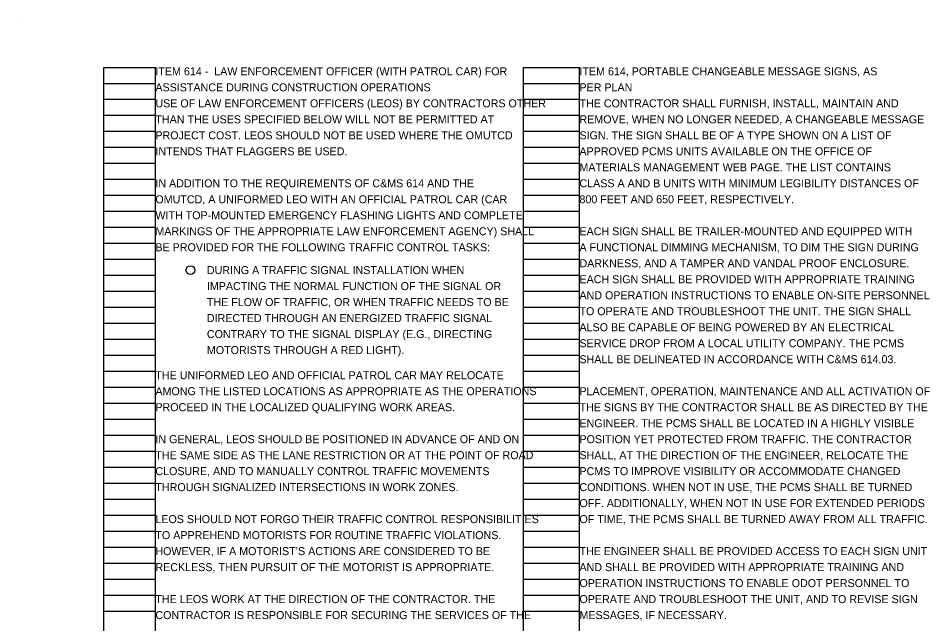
# Model space of a CAD drawing. Extents: x 0 to 32, y -44 to 21.1.
# Drawn here: x 0 to 15.95, y -10.6 to 0 of the extents above; entities that cross this region are included whole.
import ezdxf

# ---------------------------------------------------------------- set-up
doc = ezdxf.new("R2010")
doc.units = 0
doc.layers.add('SH_Data', color=7, linetype='Continuous')
doc.layers.add('SH_Text', color=7, linetype='Continuous')

msp = doc.modelspace()

# ---------------------------------------------------------------- linework, layer by layer
at = {"layer": 'SH_Data'}
for p, q in [((0, 0), (0, 0)), ((1.5, -21.02), (1.5, -0.86)), ((1.5, -0.86), (2.4, -0.86)), ((2.4, -21.02), (2.4, -0.86)), ((8.84, -21.02), (8.84, -0.86)), ((8.84, -0.86), (9.82, -0.86)), ((9.82, -21.02), (9.82, -0.86)), ((1.5, -1.14), (2.4, -1.14)), ((8.84, -1.14), (9.82, -1.14)), ((1.5, -1.42), (2.4, -1.42)), ((8.84, -1.42), (9.82, -1.42)), ((1.5, -1.7), (2.4, -1.7)), ((8.84, -1.7), (9.82, -1.7)), ((1.5, -1.98), (2.4, -1.98)), ((8.84, -1.98), (9.82, -1.98)), ((1.5, -2.26), (2.4, -2.26)), ((8.84, -2.26), (9.82, -2.26)), ((1.5, -2.54), (2.4, -2.54)), ((8.84, -2.54), (9.82, -2.54)), ((1.5, -2.82), (2.4, -2.82)), ((8.84, -2.82), (9.82, -2.82)), ((1.5, -3.1), (2.4, -3.1)), ((8.84, -3.1), (9.82, -3.1)), ((1.5, -3.38), (2.4, -3.38)), ((8.84, -3.38), (9.82, -3.38)), ((1.5, -3.66), (2.4, -3.66)), ((8.84, -3.66), (9.82, -3.66)), ((1.5, -3.94), (2.4, -3.94)), ((8.84, -3.94), (9.82, -3.94)), ((1.5, -4.22), (2.4, -4.22)), ((8.84, -4.22), (9.82, -4.22)), ((1.5, -4.5), (2.4, -4.5)), ((8.84, -4.5), (9.82, -4.5)), ((1.5, -4.78), (2.4, -4.78)), ((8.84, -4.78), (9.82, -4.78)), ((1.5, -5.06), (2.4, -5.06)), ((8.84, -5.06), (9.82, -5.06)), ((1.5, -5.34), (2.4, -5.34)), ((8.84, -5.34), (9.82, -5.34)), ((1.5, -5.62), (2.4, -5.62)), ((8.84, -5.62), (9.82, -5.62)), ((1.5, -5.9), (2.4, -5.9)), ((8.84, -5.9), (9.82, -5.9)), ((1.5, -6.18), (2.4, -6.18)), ((8.84, -6.18), (9.82, -6.18)), ((1.5, -6.46), (2.4, -6.46)), ((8.84, -6.46), (9.82, -6.46)), ((1.5, -6.74), (2.4, -6.74)), ((8.84, -6.74), (9.82, -6.74)), ((1.5, -7.02), (2.4, -7.02)), ((8.84, -7.02), (9.82, -7.02)), ((1.5, -7.3), (2.4, -7.3)), ((8.84, -7.3), (9.82, -7.3)), ((1.5, -7.58), (2.4, -7.58)), ((8.84, -7.58), (9.82, -7.58)), ((1.5, -7.86), (2.4, -7.86)), ((8.84, -7.86), (9.82, -7.86)), ((1.5, -8.14), (2.4, -8.14)), ((8.84, -8.14), (9.82, -8.14)), ((1.5, -8.42), (2.4, -8.42)), ((8.84, -8.42), (9.82, -8.42)), ((1.5, -8.7), (2.4, -8.7)), ((8.84, -8.7), (9.82, -8.7)), ((1.5, -8.98), (2.4, -8.98)), ((8.84, -8.98), (9.82, -8.98)), ((1.5, -9.26), (2.4, -9.26)), ((8.84, -9.26), (9.82, -9.26)), ((1.5, -9.54), (2.4, -9.54)), ((8.84, -9.54), (9.82, -9.54)), ((1.5, -9.82), (2.4, -9.82)), ((8.84, -9.82), (9.82, -9.82)), ((1.5, -10.1), (2.4, -10.1)), ((8.84, -10.1), (9.82, -10.1)), ((1.5, -10.38), (2.4, -10.38)), ((8.84, -10.38), (9.82, -10.38))]:
    msp.add_line(p, q, dxfattribs=at)
at = {"layer": 'SH_Text'}
msp.add_circle((3.013, -4.41), 0.0775, dxfattribs=at)

# ---------------------------------------------------------------- texts
for s, p in [('ITEM 614 -  LAW ENFORCEMENT OFFICER (WITH PATROL CAR) FOR ', (2.4, -1)), ('ITEM 614, PORTABLE CHANGEABLE MESSAGE SIGNS, AS', (9.82, -1)), ('ASSISTANCE DURING CONSTRUCTION OPERATIONS', (2.4, -1.28)), ('PER PLAN', (9.82, -1.28)), ('USE OF LAW ENFORCEMENT OFFICERS (LEOS) BY CONTRACTORS OTHER ', (2.4, -1.56)), ('THE CONTRACTOR SHALL FURNISH, INSTALL, MAINTAIN AND', (9.82, -1.56)), ('THAN THE USES SPECIFIED BELOW WILL NOT BE PERMITTED AT ', (2.4, -1.84)), ('REMOVE, WHEN NO LONGER NEEDED, A CHANGEABLE MESSAGE', (9.82, -1.84)), ('PROJECT COST. LEOS SHOULD NOT BE USED WHERE THE OMUTCD ', (2.4, -2.12)), ('SIGN. THE SIGN SHALL BE OF A TYPE SHOWN ON A LIST OF', (9.82, -2.12)), ('INTENDS THAT FLAGGERS BE USED.', (2.4, -2.4)), ('APPROVED PCMS UNITS AVAILABLE ON THE OFFICE OF', (9.82, -2.4)), ('MATERIALS MANAGEMENT WEB PAGE. THE LIST CONTAINS', (9.82, -2.68)), ('IN ADDITION TO THE REQUIREMENTS OF C&MS 614 AND THE ', (2.4, -2.96)), ('CLASS A AND B UNITS WITH MINIMUM LEGIBILITY DISTANCES OF', (9.82, -2.96)), ('OMUTCD, A UNIFORMED LEO WITH AN OFFICIAL PATROL CAR (CAR ', (2.4, -3.24)), ('800 FEET AND 650 FEET, RESPECTIVELY.', (9.82, -3.24)), ('WITH TOP-MOUNTED EMERGENCY FLASHING LIGHTS AND COMPLETE ', (2.4, -3.52)), ('MARKINGS OF THE APPROPRIATE LAW ENFORCEMENT AGENCY) SHALL ', (2.4, -3.8)), ('EACH SIGN SHALL BE TRAILER-MOUNTED AND EQUIPPED WITH', (9.82, -3.8)), ('BE PROVIDED FOR THE FOLLOWING TRAFFIC CONTROL TASKS:', (2.4, -4.08)), ('A FUNCTIONAL DIMMING MECHANISM, TO DIM THE SIGN DURING', (9.82, -4.08)), ('DARKNESS, AND A TAMPER AND VANDAL PROOF ENCLOSURE.', (9.82, -4.36)), ('DURING A TRAFFIC SIGNAL INSTALLATION WHEN ', (3.301, -4.48)), ('IMPACTING THE NORMAL FUNCTION OF THE SIGNAL OR ', (3.301, -4.76)), ('EACH SIGN SHALL BE PROVIDED WITH APPROPRIATE TRAINING', (9.82, -4.64)), ('AND OPERATION INSTRUCTIONS TO ENABLE ON-SITE PERSONNEL', (9.82, -4.92)), ('THE FLOW OF TRAFFIC, OR WHEN TRAFFIC NEEDS TO BE ', (3.301, -5.04)), ('TO OPERATE AND TROUBLESHOOT THE UNIT. THE SIGN SHALL', (9.82, -5.2)), ('DIRECTED THROUGH AN ENERGIZED TRAFFIC SIGNAL ', (3.301, -5.32)), ('ALSO BE CAPABLE OF BEING POWERED BY AN ELECTRICAL', (9.82, -5.48)), ('CONTRARY TO THE SIGNAL DISPLAY (E.G., DIRECTING ', (3.301, -5.6)), ('MOTORISTS THROUGH A RED LIGHT). ', (3.301, -5.88)), ('SERVICE DROP FROM A LOCAL UTILITY COMPANY. THE PCMS', (9.82, -5.76)), ('SHALL BE DELINEATED IN ACCORDANCE WITH C&MS 614.03.', (9.82, -6.04)), ('THE UNIFORMED LEO AND OFFICIAL PATROL CAR MAY RELOCATE ', (2.4, -6.32)), ('AMONG THE LISTED LOCATIONS AS APPROPRIATE AS THE OPERATIONS ', (2.4, -6.6)), ('PLACEMENT, OPERATION, MAINTENANCE AND ALL ACTIVATION OF', (9.82, -6.6)), ('PROCEED IN THE LOCALIZED QUALIFYING WORK AREAS.', (2.4, -6.88)), ('THE SIGNS BY THE CONTRACTOR SHALL BE AS DIRECTED BY THE', (9.82, -6.88)), ('ENGINEER. THE PCMS SHALL BE LOCATED IN A HIGHLY VISIBLE', (9.82, -7.16)), ('IN GENERAL, LEOS SHOULD BE POSITIONED IN ADVANCE OF AND ON ', (2.4, -7.44)), ('POSITION YET PROTECTED FROM TRAFFIC. THE CONTRACTOR', (9.82, -7.44)), ('THE SAME SIDE AS THE LANE RESTRICTION OR AT THE POINT OF ROAD ', (2.4, -7.72)), ('SHALL, AT THE DIRECTION OF THE ENGINEER, RELOCATE THE', (9.82, -7.72)), ('CLOSURE, AND TO MANUALLY CONTROL TRAFFIC MOVEMENTS ', (2.4, -8)), ('PCMS TO IMPROVE VISIBILITY OR ACCOMMODATE CHANGED', (9.82, -8)), ('THROUGH SIGNALIZED INTERSECTIONS IN WORK ZONES. ', (2.4, -8.28)), ('CONDITIONS. WHEN NOT IN USE, THE PCMS SHALL BE TURNED', (9.82, -8.28)), ('OFF. ADDITIONALLY, WHEN NOT IN USE FOR EXTENDED PERIODS', (9.82, -8.56)), ('LEOS SHOULD NOT FORGO THEIR TRAFFIC CONTROL RESPONSIBILITIES ', (2.4, -8.84)), ('OF TIME, THE PCMS SHALL BE TURNED AWAY FROM ALL TRAFFIC.', (9.82, -8.84)), ('TO APPREHEND MOTORISTS FOR ROUTINE TRAFFIC VIOLATIONS. ', (2.4, -9.12)), ('HOWEVER, IF A MOTORIST’S ACTIONS ARE CONSIDERED TO BE ', (2.4, -9.4)), ('THE ENGINEER SHALL BE PROVIDED ACCESS TO EACH SIGN UNIT', (9.82, -9.4)), ('RECKLESS, THEN PURSUIT OF THE MOTORIST IS APPROPRIATE. ', (2.4, -9.68)), ('AND SHALL BE PROVIDED WITH APPROPRIATE TRAINING AND', (9.82, -9.68)), ('OPERATION INSTRUCTIONS TO ENABLE ODOT PERSONNEL TO', (9.82, -9.96)), ('THE LEOS WORK AT THE DIRECTION OF THE CONTRACTOR. THE ', (2.4, -10.24)), ('OPERATE AND TROUBLESHOOT THE UNIT, AND TO REVISE SIGN', (9.82, -10.24)), ('CONTRACTOR IS RESPONSIBLE FOR SECURING THE SERVICES OF THE ', (2.4, -10.52)), ('MESSAGES, IF NECESSARY.', (9.82, -10.52))]:
    msp.add_text(s, height=0.14, dxfattribs=at).set_placement(p)

doc.saveas('drawing.dxf')
